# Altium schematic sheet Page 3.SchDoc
size 431 x 279 mm; Date: Not shown in title block; ApprovedBy: Not shown in title block; CheckedBy: Not shown in title block; Author: Not shown in title block; CompanyName: Not shown in title block; Engineer: Not shown in title block; Organization: Not shown in title block; Address1: Not shown in title block; Address2: Not shown in title block; Address3: Not shown in title block; Address4: Not shown in title block; DocumentNumber: 1; Revision: Use project parameter SCH_Rev; SheetNumber: 2; SheetTotal: 3; PageSetup: Record=PageOptions¦CenterHorizontal=True¦CenterVertical=True¦PrintScale=1.00¦XCorrection=1.00¦YCorrection=1.00¦PrintKind=0¦BorderSize=5000000¦LeftOffset=0¦BottomOffset=0¦Orientation=2¦PaperLength=1000¦PaperWidth=1000¦Scale=100¦PaperSource=15¦PrintQuality=600¦MediaType=1¦DitherType=10¦PaperKind=Letter¦PrintScaleMode=1
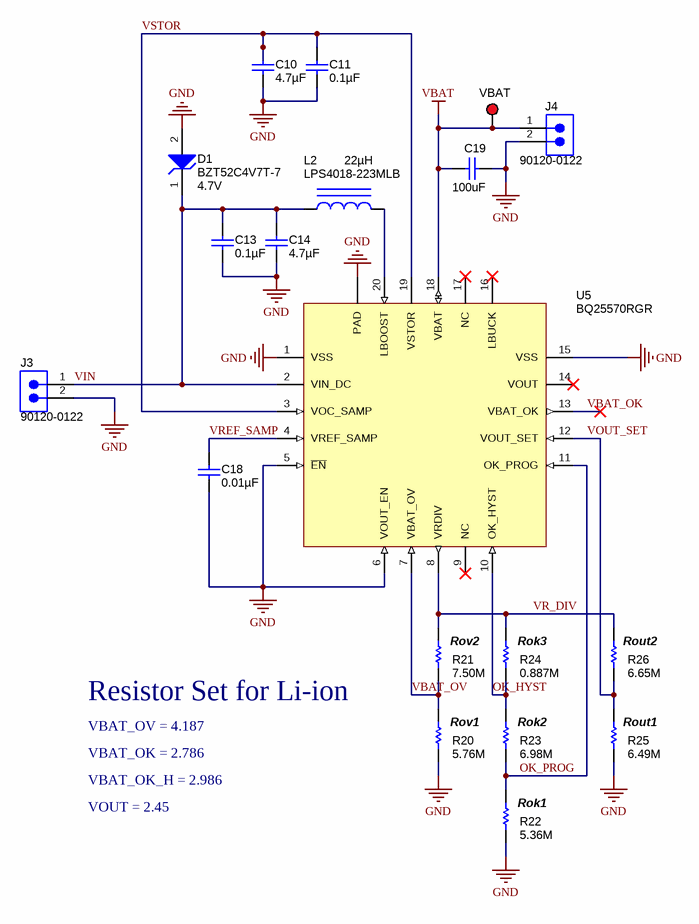
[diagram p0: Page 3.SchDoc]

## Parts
C10  ValueDisplayed: 4.7µF  [0402L]  (hidden comment: C1005X5R0J475M050BC)
C11  ValueDisplayed: 0.1µF  [0402L]  (hidden comment: GRM155R71A104KA01D)
C13  ValueDisplayed: 0.1µF  [0402L]  (hidden comment: GRM155R71A104KA01D)
C14  ValueDisplayed: 4.7µF  [0402L]  (hidden comment: C1005X5R0J475M050BC)
C18  ValueDisplayed: 0.01µF  [0402L]  (hidden comment: GRM155R61A103KA01D)
C19  value 100uF  [1210]  (hidden comment: C1210C107M9PACTU)
D1  BZT52C4V7T-7  value 4.7V  [SOD-523]
J3  90120-0122  [CONN_90120-0122]
J4  90120-0122  [CONN_90120-0122]
L2  LPS4018-223MLB  ValueDisplayed: 22µH  [LPS4018]
R20  ValueDisplayed: 5.76M  [0402L]  (hidden comment: CRCW04025M76FKED)
R21  ValueDisplayed: 7.50M  [0402L]  (hidden comment: CRCW04027M50FKED)
R22  ValueDisplayed: 5.36M  [0402L]  (hidden comment: CRCW04025M36FKED)
R23  ValueDisplayed: 6.98M  [0402L]  (hidden comment: CRCW04026M98FKED)
R24  ValueDisplayed: 0.887M  [0402L]  (hidden comment: CRCW0402887RFKED)
R25  ValueDisplayed: 6.49M  [0402L]  (hidden comment: CRCW04026M49FKED)
R26  ValueDisplayed: 6.65M  [0402L]  (hidden comment: CRCW04026M65FKED)
U5  BQ25570RGR  [RGR0020A]
VBAT  5000  [Keystone5000]  (value not drawn)

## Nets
GND: C10.2 C11.2 C13.2 C14.2 C18.2 C19.1 D1.2(A) J3.2 J4.2 R20.1 R22.1 R25.1 U5.1(VSS) U5.5(~{EN}) U5.6(VOUT_EN) U5.15(VSS) U5.21(PAD)
VBAT: C19.2 J4.1 U5.18(VBAT) VBAT.1
OK_HYST: R23.2 R24.1 U5.10(OK_HYST)
OK_PROG: R22.2 R23.1 U5.11(OK_PROG)
VBAT_OK: U5.13(VBAT_OK)
VBAT_OV: R20.2 R21.1 U5.7(VBAT_OV)
VIN: C13.1 C14.1 D1.1(K) J3.1 L2.1 U5.2(VIN_DC)
VOUT_SET: R25.2 R26.1 U5.12(VOUT_SET)
VR_DIV: R21.2 R24.2 R26.2 U5.8(VRDIV)
VREF_SAMP: C18.1 U5.4(VREF_SAMP)
VSTOR: C10.1 C11.1 U5.3(VOC_SAMP) U5.19(VSTOR)
NetL2_2: L2.2 U5.20(LBOOST)

Not connected (* = marked no-connect by the designer): U5 9(NC)* 14(VOUT)* 16(LBUCK)* 17(NC)*

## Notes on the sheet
- (near R21) Rov2
- (near R24) Rok3
- (near R26) Rout2
- VBAT_OV = 4.187
- VBAT_OK = 2.786
- Resistor Set for Li-ion
- (near R20) Rov1
- (near R23) Rok2
- (near R25) Rout1
- VBAT_OK_H = 2.986
- VOUT = 2.45
- (near R22) Rok1

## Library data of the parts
C10 C14 = C1005X5R0J475M050BC: CAP, CERM, 4.7uF, 6.3V, +/-20%, X5R, 0402; Manufacturer: TDK; Polarized: N; CompType: Capacitor; U/M: EA; Cap_F: 0.0000047; Tolerance_%: 20; Value1: Unknown; VDC_V: 6.3; TaMin_C: -55; TaMax_C: 85; Cap_Case: 0402
C11 C13 = GRM155R71A104KA01D: CAP, CERM, 0.1uF, 10V, +/-10%, X7R, 0402; Manufacturer: MuRata; Polarized: N; CompType: Capacitor; U/M: EA; Cap_F: 0.0000001; Tolerance_%: 10; Value1: Unknown; TaMin_C: -55; TaMax_C: 125; Cap_Case: 0402
C18 = GRM155R61A103KA01D: CAP, CERM, 0.01uF, 10V, +/-10%, X5R, 0402; Manufacturer: MuRata; Polarized: N; CompType: Capacitor; U/M: EA; Cap_F: 0.00000001; Tolerance_%: 10; Value1: Unknown; TaMin_C: -55; TaMax_C: 85; Cap_Case: 0402
C19 = C1210C107M9PACTU: CAP, CERM, 100uF, 6.3V, +/-20%, X5R, 1210; Manufacturer: Kemet; Polarized: N; CompType: Capacitor; ValueDisplayed: DNP; U/M: EA; Cap_F: 0.0001; Tolerance_%: 20; Value1: Unknown; VDC_V: 6.3; TaMin_C: -55; TaMax_C: 85
D1 = BZT52C4V7T-7: Diode, Zener, 4.7V, 300mW, SOD-523; Manufacturer: Diodes Inc.; U/M: EA; Power_W: 0.3; Vz_V: 4.7; Value1: 0.3W; RJA_CperW: 417
J3 J4 = 90120-0122: Header, 100mil, 2x1, Tin plated, TH; Manufacturer: Molex; SymbolCreator: a0412235; U/M: EA
L2 = LPS4018-223MLB: Inductor, Shielded Drum Core, Ferrite, 22uH, 0.83A, 0.36 ohm, SMD; Manufacturer: Coilcraft; Ind_H: 22.0E-6; Imax_A: 0.83; Irms: 0.9A @ 40C rise; Isat: 0.83A @ 30% inductance drop; DCR_ohm: 0.36; U/M: EA
R20 = CRCW04024M75FKED: RES, 5.76 M, 1%, 0.063 W, 0402; Manufacturer: Vishay-Dale; CompType: Resistor; Value: 5.76Meg; Res_ohm: 5760000; Value_Code: 5M76; Tolerance_%: 1; Power_W: 0.063; Value2: 0.063W; VDC_V: 50; TempCo: 100 ppm/C; EIA_Code: E96; U/M: EA
R21 = CRCW04028M45FKED: RES, 7.50 M, 1%, 0.063 W, 0402; Manufacturer: Vishay-Dale; CompType: Resistor; Value: 7.50Meg; Res_ohm: 7500000; Value_Code: 7M50; Tolerance_%: 1; Power_W: 0.063; Value2: 0.063W; VDC_V: 50; TempCo: 100 ppm/C; EIA_Code: E96; U/M: EA
R22 = CRCW04022M10FKED: RES, 5.36 M, 1%, 0.063 W, 0402; Manufacturer: Vishay-Dale; CompType: Resistor; Value: 5.36Meg; Res_ohm: 5360000; Value_Code: 5M36; Tolerance_%: 1; Power_W: 0.063; Value2: 0.063W; VDC_V: 50; TempCo: 100 ppm/C; EIA_Code: E96; U/M: EA
R23 = CRCW04024M99FKED: RES, 4.99 M, 1%, 0.063 W, 0402; Manufacturer: Vishay-Dale; CompType: Resistor; Value: 4.99Meg; Res_ohm: 6980000; Value_Code: 6M98; Tolerance_%: 1; Power_W: 0.063; Value2: 0.063W; VDC_V: 50; TempCo: 100 ppm/C; EIA_Code: E96; U/M: EA
R24 = CRCW04021M27FKED: RES, 0.887 M, 1%, 0.063 W, 0402; Manufacturer: Vishay-Dale; CompType: Resistor; Value: 0.887Meg; Res_ohm: 887000; Value_Code: 0M887; Tolerance_%: 1; Power_W: 0.063; Value2: 0.063W; VDC_V: 50; TempCo: 100 ppm/C; EIA_Code: E96; U/M: EA
R25 = CRCW04026M49FKED: RES, 6.49 M, 1%, 0.063 W, 0402; Manufacturer: Vishay-Dale; CompType: Resistor; Value: 6.49Meg; Res_ohm: 6490000; Value_Code: 6M49; Tolerance_%: 1; Power_W: 0.063; Value2: 0.063W; VDC_V: 50; TempCo: 100 ppm/C; EIA_Code: E96; U/M: EA
R26 = CRCW04026M65FKED: RES, 6.65 M, 1%, 0.063 W, 0402; Manufacturer: Vishay-Dale; CompType: Resistor; Value: 6.65Meg; Res_ohm: 6650000; Value_Code: 6M65; Tolerance_%: 1; Power_W: 0.063; Value2: 0.063W; VDC_V: 50; TempCo: 100 ppm/C; EIA_Code: E96; U/M: EA
U5 = BQ25570RGR: Ultra Low Power Harvester Power Management IC with Boost Charger, and Nano-Powered Buck Converter, RGR0020A; Alternate Manufacturer: None; Manufacturer: Texas Instruments; SymbolCreator: a0412235; U/M: EA
VBAT = 5000: Test Point, Miniature, Red, TH; Manufacturer: Keystone; CompType: Test Point Loop; U/M: EA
